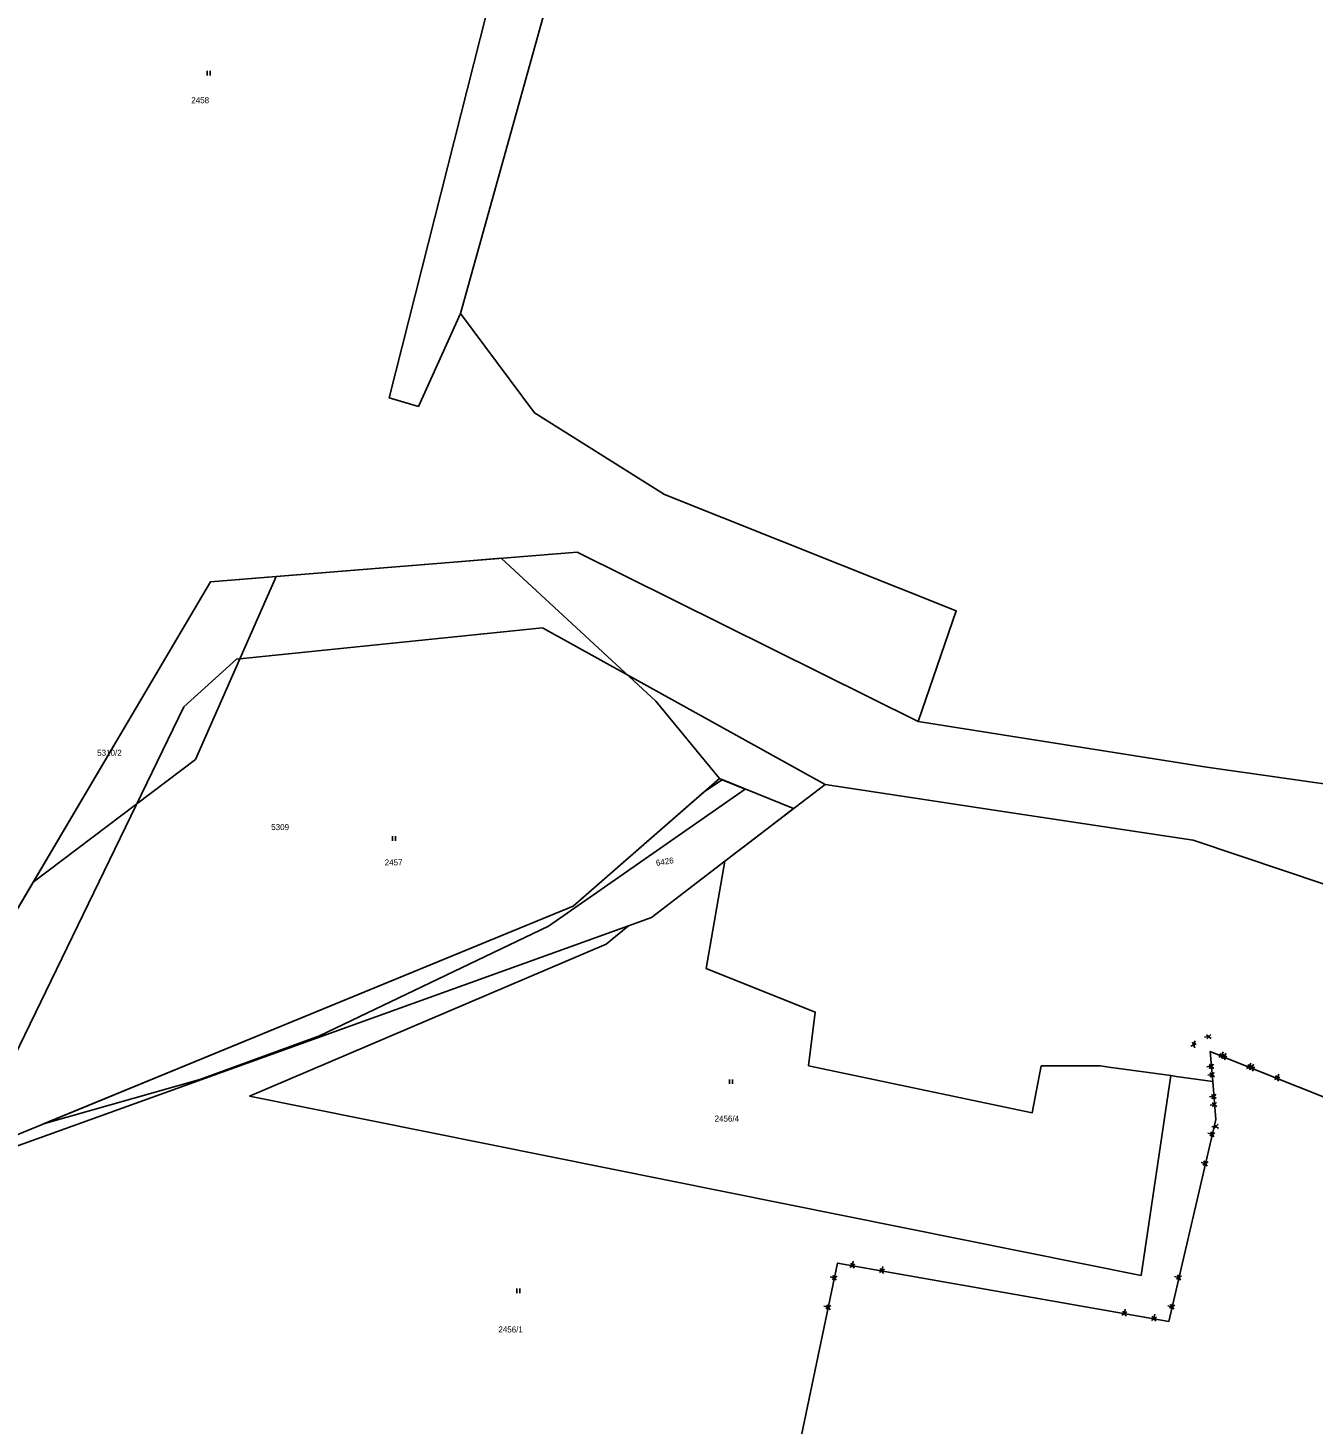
# Model space of a CAD drawing. Extents: x -439750 to -439180, y -1258684 to -1258308.
# Drawn here: x -439386.7 to -439301.1, y -1258628.9 to -1258535.8 of the extents above; entities that cross this region are included whole.
import ezdxf

# ---------------------------------------------------------------- set-up
doc = ezdxf.new("R2010")
doc.units = 0
for name, color, linetype in [('KATASTER', 7, 'Continuous'), ('TARCHY', 7, 'Continuous'), ('UOV', 7, 'Continuous')]:
    doc.layers.add(name, color=color, linetype=linetype)

# ---------------------------------------------------------------- blocks, each defined once
blk = doc.blocks.new('306')
for p, q in [((-0.5, 1.5), (-0.5, 0)), ((0.5, 0), (0.5, 1.5))]:
    blk.add_line(p, q)
blk = doc.blocks.new('2072')
for p, q in [((-4.3, 0.7), (-5.7, -0.7)), ((-5.7, 0.7), (-4.3, -0.7)), ((-5, 0), (-5, -1.5)), ((4.3, 0.7), (5.7, -0.7)), ((5.7, 0.7), (4.3, -0.7)), ((5, 0), (5, -1.5))]:
    blk.add_line(p, q)

msp = doc.modelspace()

# ---------------------------------------------------------------- linework, layer by layer
at = {"layer": 'KATASTER'}
for points in [[(-439378.69, -1258503.81), (-439348.78, -1258505.65), (-439344.2, -1258505.65), (-439347.2, -1258516.43), (-439357.91, -1258554.88), (-439352.98, -1258561.5), (-439344.31, -1258566.93), (-439324.86, -1258574.68), (-439327.4, -1258582.06), (-439350.12, -1258570.77), (-439374.58, -1258572.75), (-439396.15, -1258609.27), (-439391.21, -1258611.67), (-439390.74, -1258613.33), (-439393.1, -1258624.81), (-439431.15, -1258626.74), (-439430.73, -1258625.37), (-439384.01, -1258511.1)], [(-439391.21, -1258611.67), (-439376.35, -1258581.07), (-439372.84, -1258577.9), (-439352.45, -1258575.82), (-439333.61, -1258586.25), (-439340.29, -1258591.37), (-439345.17, -1258595.12), (-439346.71, -1258595.67)], [(-439371.96, -1258607.01), (-439348.19, -1258596.88), (-439346.71, -1258595.67), (-439345.17, -1258595.12), (-439340.29, -1258591.37), (-439341.53, -1258598.52), (-439334.26, -1258601.41), (-439334.71, -1258604.99), (-439319.8, -1258608.12), (-439319.2, -1258605), (-439315.25, -1258605), (-439314.69, -1258605.08), (-439310.57, -1258605.65), (-439312.54, -1258618.96)], [(-439391.21, -1258611.67), (-439346.71, -1258595.67), (-439348.19, -1258596.88), (-439371.96, -1258607.01), (-439312.54, -1258618.96), (-439310.57, -1258605.65), (-439310.21, -1258605.7), (-439307.77, -1258606.04), (-439307.57, -1258608.58), (-439310.7, -1258622.02), (-439332.77, -1258618.14), (-439337.57, -1258641.06), (-439389.53, -1258630.94), (-439393.1, -1258624.81), (-439390.74, -1258613.33)]]:
    msp.add_lwpolyline(points, close=True, dxfattribs=at)
for points in [[(-439357.91, -1258554.88), (-439360.71, -1258561.06), (-439362.66, -1258560.48), (-439348.78, -1258505.65)], [(-439293.6, -1258595.16), (-439302.92, -1258592.03), (-439309.07, -1258589.96), (-439321.61, -1258588.07), (-439333.61, -1258586.25), (-439352.45, -1258575.82), (-439372.84, -1258577.9), (-439376.35, -1258581.07), (-439391.21, -1258611.67), (-439396.15, -1258609.27), (-439374.58, -1258572.75), (-439350.12, -1258570.77), (-439327.4, -1258582.06), (-439308.16, -1258585.09), (-439288.16, -1258587.94)], [(-439561.36, -1258613.95), (-439535.34, -1258619.8), (-439494.8, -1258628.92), (-439489.89, -1258630.03), (-439433.6, -1258642.69), (-439400.45, -1258651.81), (-439363.34, -1258663.17), (-439338.38, -1258668.53), (-439337.57, -1258641.06), (-439332.77, -1258618.14), (-439310.7, -1258622.02), (-439307.57, -1258608.58), (-439307.77, -1258606.04), (-439307.94, -1258604.05), (-439306.26, -1258604.72), (-439264.71, -1258621.3), (-439225.86, -1258624.44), (-439218.252, -1258627.623)], [(-439218.252, -1258627.623), (-439225.86, -1258624.44), (-439264.71, -1258621.3), (-439306.26, -1258604.72), (-439307.94, -1258604.05), (-439307.77, -1258606.04), (-439307.57, -1258608.58), (-439310.7, -1258622.02), (-439332.77, -1258618.14), (-439337.57, -1258641.06), (-439338.38, -1258668.53), (-439363.34, -1258663.17), (-439400.45, -1258651.81), (-439433.6, -1258642.69), (-439489.89, -1258630.03), (-439494.8, -1258628.92), (-439535.34, -1258619.8), (-439561.36, -1258613.95)]]:
    msp.add_lwpolyline(points, dxfattribs=at)
at = {"layer": 'TARCHY'}
msp.add_lwpolyline([(-439385.7, -1258608.87), (-439350.39, -1258594.35), (-439341.64, -1258586.72), (-439340.47, -1258585.93), (-439338.93, -1258586.56), (-439352.04, -1258595.68), (-439367.3, -1258603), (-439375.28, -1258605.91)], close=True, dxfattribs=at)
at = {"layer": 'UOV'}
for points in [[(-439386.39, -1258592.75), (-439375.58, -1258584.59), (-439370.2, -1258572.4), (-439358.37, -1258571.44), (-439355.2, -1258571.18), (-439344.89, -1258580.71), (-439340.65, -1258585.86), (-439350.39, -1258594.35), (-439391.8, -1258611.38), (-439396.15, -1258609.27)], [(-439386.39, -1258592.75), (-439374.58, -1258572.75), (-439370.2, -1258572.4), (-439375.58, -1258584.59)], [(-439345.17, -1258595.12), (-439346.71, -1258595.67), (-439391.21, -1258611.67), (-439391.8, -1258611.38), (-439350.39, -1258594.35), (-439340.65, -1258585.86), (-439335.71, -1258587.86), (-439338.24, -1258589.8), (-439340.29, -1258591.37)]]:
    msp.add_lwpolyline(points, close=True, dxfattribs=at)

# ---------------------------------------------------------------- block references
at = {"layer": 'KATASTER', "xscale": 0.2, "yscale": 0.20000000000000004}
for p in [(-439374.7, -1258539.01), (-439362.35, -1258590), (-439339.87, -1258606.2), (-439354.05, -1258620.14)]:
    msp.add_blockref('306', p, dxfattribs=at)
at = {"layer": 'KATASTER'}
for p, xscale, yscale, rotation in [((-439308.118, -1258603.979), 0.2, 0.19999999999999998, 158.250943), ((-439307.94, -1258604.047), 0.2, 0.19999999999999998, -85.09485000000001), ((-439306.082, -1258604.791), 0.2, 0.19999999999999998, 158.250943), ((-439307.77, -1258606.043), 0.2, 0.19999999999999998, -85.09485000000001), ((-439304.402, -1258605.461), 0.2, 0.19999999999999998, 158.250943), ((-439307.727, -1258606.586), 0.2, 0.20000000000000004, -85.49592000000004), ((-439307.613, -1258608.034), 0.2, 0.20000000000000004, -85.49592000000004), ((-439308.024, -1258610.528), 0.19999999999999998, 0.2, -103.08572500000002), ((-439330.8, -1258618.486), 0.20000000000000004, 0.19999999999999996, 170.053874), ((-439333.18, -1258620.098), 0.19999999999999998, 0.20000000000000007, -101.825218), ((-439310.246, -1258620.072), 0.19999999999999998, 0.2, -103.08572500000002), ((-439312.67, -1258621.674), 0.20000000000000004, 0.19999999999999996, 170.053874)]:
    msp.add_blockref('2072', p, dxfattribs=dict(at, xscale=xscale, yscale=yscale, rotation=rotation))

# ---------------------------------------------------------------- texts
for s, p in [('2458', (-439375.852, -1258540.86)), ('2457', (-439362.962, -1258591.64)), ('2456/4', (-439340.971, -1258608.71)), ('2456/1', (-439355.385, -1258622.76))]:
    msp.add_text(s, height=0.4, dxfattribs=at).set_placement(p)
at = {"layer": 'UOV'}
for s, p in [('5310/2', (-439382.124, -1258584.34)), ('5309', (-439370.524, -1258589.29))]:
    msp.add_text(s, height=0.4, dxfattribs=at).set_placement(p)
msp.add_text('6426', height=0.4, rotation=8.995, dxfattribs=at).set_placement((-439344.847, -1258591.677))

doc.saveas('drawing.dxf')
